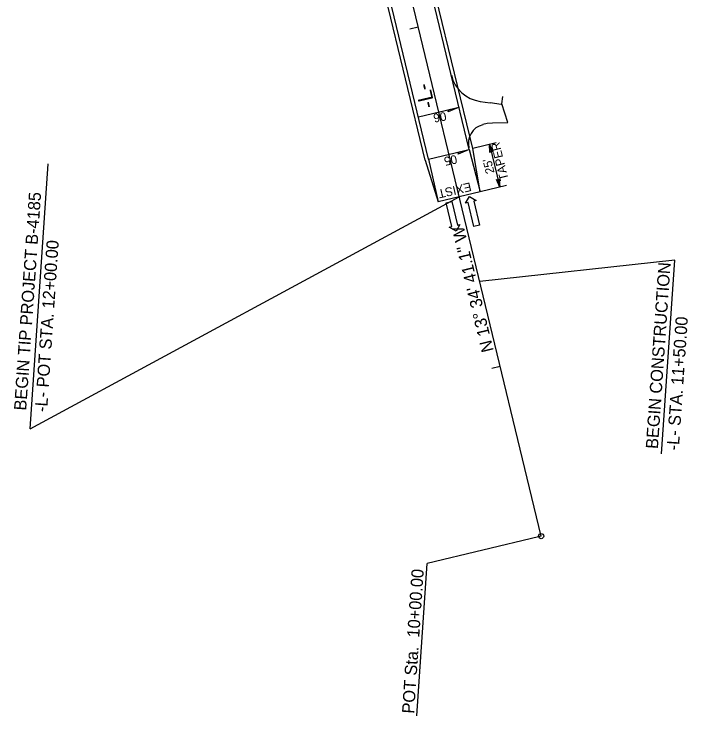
# Model space of a CAD drawing. Extents: x 2599146 to 2600072, y 728518 to 730269.
# Drawn here: x 2599256.5 to 2599642.7, y 728517.9 to 728920 of the extents above; entities that cross this region are included whole.
import ezdxf

# ---------------------------------------------------------------- set-up
doc = ezdxf.new("R2010")
doc.units = 0
for name, color, linetype in [('Old_Level_4', 7, 'Continuous'), ('Prop Dimension', 7, 'Continuous'), ('Prop Dimension Text', 7, 'Continuous'), ('Prop EOT', 7, 'Continuous'), ('Prop Horizontal Alignment', 7, 'Continuous'), ('Prop Horizontal Alignment Direction Label', 7, 'Continuous'), ('Prop Horizontal Alignment Station Label', 7, 'Continuous'), ('Prop Horizontal Alignment Tick Large', 7, 'Continuous'), ('Prop Horizontal Alignment Tick Small', 7, 'Continuous'), ('Prop SS Cut Line', 7, 'Continuous'), ('Prop Superelevation Label', 7, 'Continuous'), ('Prop Terminator CELL', 7, 'Continuous')]:
    doc.layers.add(name, color=color, linetype=linetype)

msp = doc.modelspace()

# ---------------------------------------------------------------- linework, layer by layer
at = {"layer": 'Old_Level_4'}
for p, q in [((2599515.24, 728811.62), (2599517.52, 728815.41)), ((2599517.52, 728815.41), (2599521.37, 728813.09)), ((2599504.13, 728811.84), (2599507.34, 728812.61)), ((2599507.39, 728798.23), (2599504.13, 728811.84)), ((2599507.34, 728812.61), (2599510.6, 728799)), ((2599516.7, 728811.97), (2599515.24, 728811.62)), ((2599519.96, 728798.36), (2599516.7, 728811.97)), ((2599521.37, 728813.09), (2599519.91, 728812.74)), ((2599519.91, 728812.74), (2599523.17, 728799.13)), ((2599505.93, 728797.88), (2599507.39, 728798.23)), ((2599509.78, 728795.56), (2599505.93, 728797.88)), ((2599512.06, 728799.35), (2599509.78, 728795.56)), ((2599510.6, 728799), (2599512.06, 728799.35)), ((2599523.17, 728799.13), (2599519.96, 728798.36))]:
    msp.add_line(p, q, dxfattribs=at)
at = {"layer": 'Prop Dimension'}
for p, q in [((2599532.81, 728846.14), (2599519.34, 728842.88)), ((2599528.95, 728845.2), (2599534.82, 728820.9)), ((2599538.68, 728821.84), (2599523.69, 728818.21))]:
    msp.add_line(p, q, dxfattribs=at)
at = {"layer": 'Prop EOT'}
for p, q in [((2599517.39, 728842.41), (2599481.48, 728991.13)), ((2599519.34, 728842.88), (2599483.42, 728991.6)), ((2599492.12, 728836.31), (2599456.2, 728985.02)), ((2599494.06, 728836.78), (2599458.15, 728985.49)), ((2599523.66, 728869.92), (2599529.44, 728869.08)), ((2599535.56, 728868.19), (2599529.44, 728869.08)), ((2599536.26, 728868.17), (2599535.56, 728868.19)), ((2599539.42, 728857.78), (2599536.12, 728868.62)), ((2599527.61, 728857.28), (2599525.07, 728856.62)), ((2599530.65, 728857.39), (2599527.65, 728857.28)), ((2599539.45, 728857.69), (2599530.65, 728857.39)), ((2599517.39, 728842.41), (2599523.69, 728818.21)), ((2599523.69, 728818.21), (2599519.34, 728842.88)), ((2599492.12, 728836.31), (2599499.48, 728812.37)), ((2599494.06, 728836.78), (2599499.48, 728812.37)), ((2599523.69, 728818.21), (2599499.48, 728812.37))]:
    msp.add_line(p, q, dxfattribs=at)
for centre, radius, start, end in [((2599526.54, 728889.71), 20, 193.5781, 261.7044), ((2599527.85, 728845.97), 11, 104.6246, 194.1075)]:
    msp.add_arc(centre, radius, start, end, dxfattribs=at)
at = {"layer": 'Prop Horizontal Alignment'}
msp.add_line((2599558.55, 728620.88), (2599469.81, 728988.31), dxfattribs=at)
at = {"layer": 'Prop Horizontal Alignment Station Label'}
for p, q in [((2599265.73, 728682.26), (2599276.18, 728834.13)), ((2599265.73, 728682.26), (2599511.6, 728815.29)), ((2599635.12, 728779.08), (2599523.34, 728766.69)), ((2599627.47, 728668.08), (2599635.12, 728779.08)), ((2599557.09, 728620.53), (2599493.33, 728605.13)), ((2599487.31, 728517.85), (2599493.33, 728605.13))]:
    msp.add_line(p, q, dxfattribs=at)
msp.add_circle((2599558.55, 728620.88), 1.5, dxfattribs=at)
at = {"layer": 'Prop Horizontal Alignment Tick Large'}
msp.add_line((2599558.55, 728620.88), (2599550.78, 728619.01), dxfattribs=at)
at = {"layer": 'Prop Horizontal Alignment Tick Small'}
for p, q in [((2599488.12, 728912.5), (2599483.26, 728911.33)), ((2599511.6, 728815.29), (2599506.74, 728814.12)), ((2599535.08, 728718.09), (2599530.22, 728716.92))]:
    msp.add_line(p, q, dxfattribs=at)
at = {"layer": 'Prop SS Cut Line'}
msp.add_line((2599536.12, 728868.62), (2599536.56, 728872.76), dxfattribs=at)
at = {"layer": 'Prop Superelevation Label'}
for p, q in [((2599488.2, 728861.08), (2599511.52, 728866.71)), ((2599494.06, 728836.78), (2599517.39, 728842.41))]:
    msp.add_line(p, q, dxfattribs=at)
at = {"layer": 'Prop Terminator CELL'}
for points in [[(2599511.52, 728866.71), (2599505.21, 728863.95), (2599505.77, 728865.32)], [(2599517.39, 728842.41), (2599511.08, 728839.65), (2599511.63, 728841.02)], [(2599529.25, 728840.65), (2599528.95, 728845.2), (2599530.79, 728840.99), (2599529.88, 728841.36)], [(2599534.52, 728825.46), (2599534.82, 728820.9), (2599532.98, 728825.11), (2599533.89, 728824.74)]]:
    msp.add_lwpolyline(points, close=True, dxfattribs=at)

# ---------------------------------------------------------------- texts
at = {"layer": 'Prop Dimension Text'}
for s, p in [('TAPER', (2599539.92, 728825.33)), ("25'", (2599531.89, 728829.13))]:
    msp.add_text(s, height=5, rotation=103.9129, dxfattribs=at).set_placement(p)
at = {"layer": 'Prop Horizontal Alignment Direction Label'}
msp.add_text('N 13%%d 34\' 41.1" W', height=7, rotation=103.5781, dxfattribs=at).set_placement((2599531.45, 728727.16))
at = {"layer": 'Prop Horizontal Alignment Station Label'}
for s, height, rotation, p in [('-L-', 8.75, 103.1299, (2599497.8, 728867.02)), ('BEGIN TIP PROJECT B-4185', 7, 86.05, (2599263.47, 728692.68)), ('-L- POT STA. 12+00.00', 7, 86.05, (2599275.44, 728691.86)), ('BEGIN CONSTRUCTION', 7, 86.0601, (2599625.44, 728670.68)), ('-L- STA. 11+50.00', 7, 86.0601, (2599637.41, 728669.86)), ('POT Sta.  10+00.00', 7, 86.1491, (2599485.78, 728519.03))]:
    msp.add_text(s, height=height, rotation=rotation, dxfattribs=at).set_placement(p)
at = {"layer": 'Prop Superelevation Label'}
for s, rotation, p in [('06', 190.5486, (2599503.72, 728864.02)), ('05', 191.6993, (2599509.8, 728839.39)), ('EXIST.', 193.1015, (2599517.89, 728823.61))]:
    msp.add_text(s, height=5, rotation=rotation, dxfattribs=at).set_placement(p)

doc.saveas('drawing.dxf')
